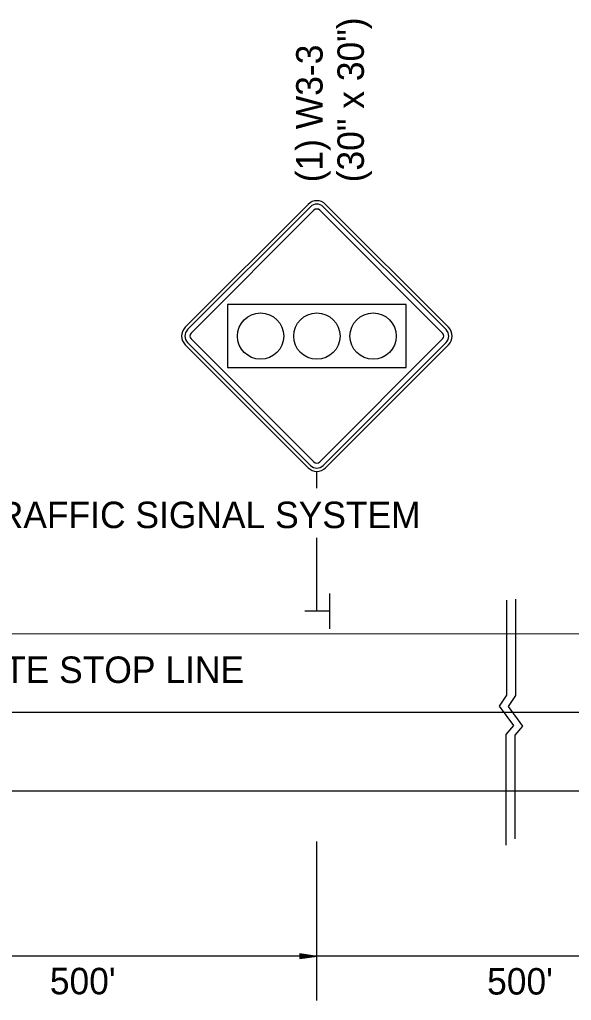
# Model space of a CAD drawing. Extents: x 1927831 to 1930787, y 596452 to 597699.
# Drawn here: x 1927956.5 to 1928081.6, y 596954.3 to 597176.4 of the extents above; entities that cross this region are included whole.
import ezdxf

# ---------------------------------------------------------------- set-up
doc = ezdxf.new("R2010")
doc.units = 0
for name, color, linetype in [('Default', 7, 'Continuous'), ('P_TC_Signs_Permanent', 7, 'Continuous'), ('R_Border', 7, 'Continuous')]:
    doc.layers.add(name, color=color, linetype=linetype)

msp = doc.modelspace()

# ---------------------------------------------------------------- linework, layer by layer
at = {"layer": 'Default'}
for p, q in [((1928026.77, 597046.42), (1928026.77, 597038.42)), ((1928026.65, 597042.44), (1928021.19, 597042.44)), ((1927841.07, 597037.34), (1928485.68, 597037.29)), ((1927840.35, 597019.55), (1928622.79, 597019.49)), ((1927840.85, 597001.76), (1927994.96, 597001.76)), ((1927840.85, 597001.76), (1928485.68, 597001.71)), ((1928023.92, 596954.25), (1928023.92, 596990.28)), ((1928023.92, 596964.29), (1927922.79, 596964.29)), ((1928020.08, 596964.87), (1928023.92, 596964.29)), ((1928020.08, 596964.87), (1928020.08, 596963.71)), ((1928020.08, 596964.77), (1928023.28, 596964.29)), ((1928020.08, 596964.67), (1928022.62, 596964.29)), ((1928020.08, 596964.58), (1928021.98, 596964.29)), ((1928020.08, 596964.48), (1928021.33, 596964.29)), ((1928020.08, 596964.38), (1928020.69, 596964.29)), ((1928020.08, 596963.71), (1928023.92, 596964.29)), ((1928020.08, 596964.1), (1928021.33, 596964.29)), ((1928020.08, 596963.91), (1928022.62, 596964.29)), ((1928020.08, 596963.81), (1928023.28, 596964.29)), ((1928020.08, 596964), (1928021.98, 596964.29)), ((1928020.08, 596964.2), (1928020.69, 596964.29)), ((1928122.82, 596964.29), (1928023.06, 596964.29))]:
    msp.add_line(p, q, dxfattribs=at)
for points in [[(1928066.89, 597044.92), (1928066.89, 597023.4), (1928065.23, 597020.93), (1928068.47, 597016.5), (1928066.76, 597014.45), (1928066.76, 596989.43)], [(1928068.93, 597045.12), (1928068.93, 597023.32), (1928067.27, 597020.84), (1928070.51, 597016.41), (1928068.81, 597014.37), (1928068.8, 596990.87)]]:
    msp.add_lwpolyline(points, dxfattribs=at)
at = {"layer": 'P_TC_Signs_Permanent'}
for p, q in [((1927994.09, 597106.74), (1928021.93, 597134.58)), ((1927994.62, 597106.21), (1928022.46, 597134.05)), ((1928023.26, 597133.26), (1927995.41, 597105.42)), ((1928052.42, 597105.42), (1928024.58, 597133.26)), ((1928025.38, 597134.05), (1928053.22, 597106.21)), ((1928025.91, 597134.58), (1928053.75, 597106.74)), ((1927995.41, 597104.09), (1928023.26, 597076.25)), ((1928024.58, 597076.25), (1928052.42, 597104.09)), ((1928021.93, 597074.92), (1927994.09, 597102.77)), ((1928022.46, 597075.45), (1927994.62, 597103.3)), ((1928053.22, 597103.3), (1928025.38, 597075.45)), ((1928053.75, 597102.77), (1928025.91, 597074.92))]:
    msp.add_line(p, q, dxfattribs=at)
msp.add_lwpolyline([(1928044.17, 597097.63), (1928044.17, 597111.88), (1928003.67, 597111.88), (1928003.67, 597097.63)], close=True, dxfattribs=at)
for centre in [(1928011.17, 597104.75), (1928023.92, 597104.75), (1928036.67, 597104.75)]:
    msp.add_circle(centre, 5.25, dxfattribs=at)
for centre, radius, start, end in [((1928023.92, 597132.6), 2.81, 45, 135), ((1928023.92, 597132.6), 2.06, 45, 135), ((1928023.92, 597132.6), 0.937, 45, 135), ((1927996.08, 597104.75), 2.81, 135, 225), ((1927996.08, 597104.75), 2.06, 135, 225), ((1928051.76, 597104.75), 2.06, 315, 45), ((1928051.76, 597104.75), 2.81, 315, 45), ((1927996.08, 597104.75), 0.937, 135, 225), ((1928051.76, 597104.75), 0.938, 315, 45), ((1928023.92, 597076.91), 2.06, 225, 315), ((1928023.92, 597076.91), 0.938, 225, 315), ((1928023.92, 597076.91), 2.81, 225, 315)]:
    msp.add_arc(centre, radius, start, end, dxfattribs=at)
at = {"layer": 'R_Border'}
for p, q in [((1928023.92, 597070.33), (1928023.92, 597074.1)), ((1928023.92, 597042.44), (1928023.92, 597059.06))]:
    msp.add_line(p, q, dxfattribs=at)

# ---------------------------------------------------------------- texts
at = {"layer": 'Default'}
for s, rotation, p in [('PORTABLE TRAFFIC SIGNAL SYSTEM', 360, (1927901.66, 597061.24)), ('12" WHITE STOP LINE', 360, (1927923.42, 597026.16)), ("500'", 359.9922, (1927963.39, 596955.63)), ("500'", 359.9922, (1928062.5, 596955.57))]:
    msp.add_text(s, height=6, rotation=rotation, dxfattribs=at).set_placement(p)
at = {"layer": 'R_Border'}
for s, height, p in [('(30" x 30")', 5.9996, (1928034.58, 597139.58)), ('(1) W3-3', 6, (1928025.22, 597139.58))]:
    msp.add_text(s, height=height, rotation=90, dxfattribs=at).set_placement(p)

doc.saveas('drawing.dxf')
